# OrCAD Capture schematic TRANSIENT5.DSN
size A
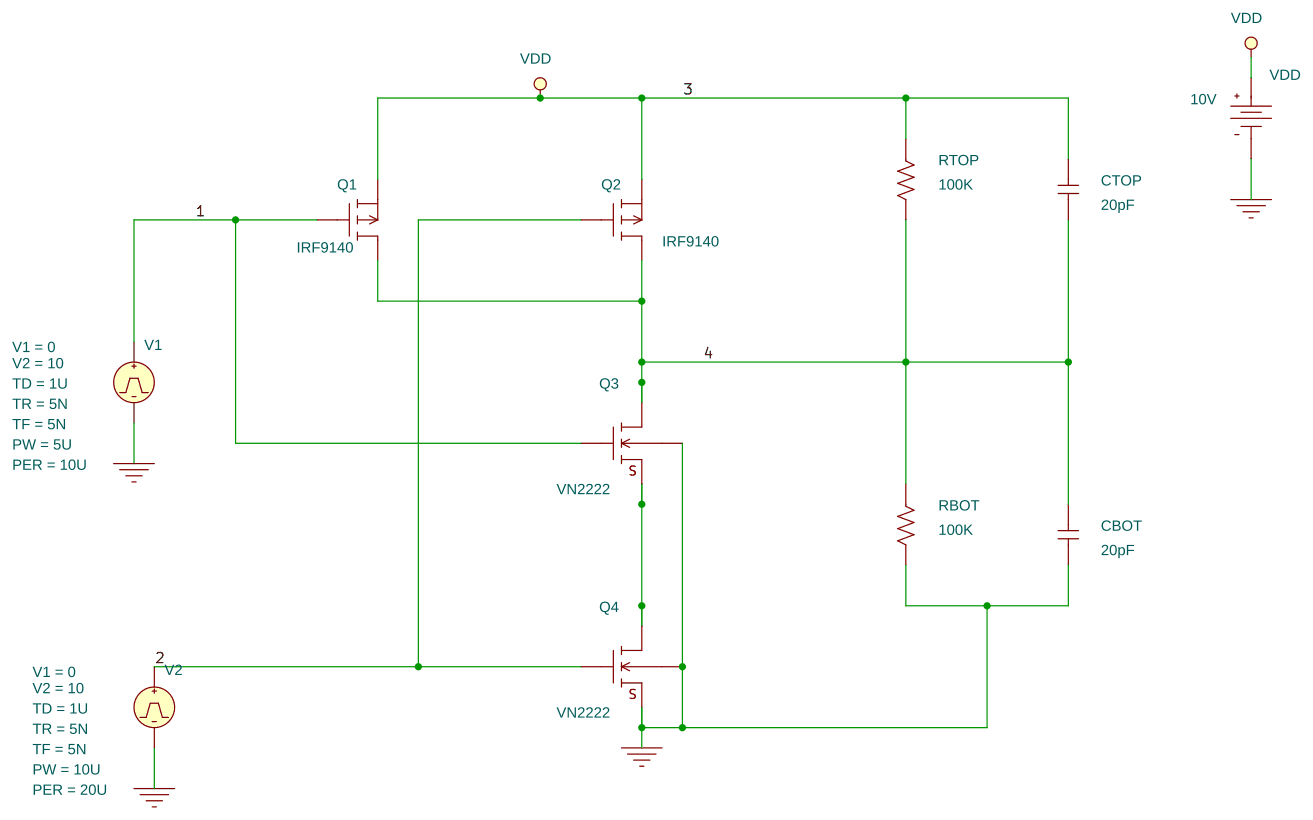
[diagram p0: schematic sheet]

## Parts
CBOT  20pF  [RAD/CK05]
CTOP  20pF  [RAD/CK05]
Q1  IRF9140  [TO204AA]
Q2  IRF9140  [TO204AA]
Q3  VN2222  [MFN4]
Q4  VN2222  [MFN4]
RBOT  100K  [AX/RC05]
RTOP  100K  [AX/RC05]
V1  VPULSE
V2  VPULSE
VDD  VDC

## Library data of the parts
CBOT CTOP = C
Q1 Q2 = IRF9140
Q3 Q4 = VN2222
RBOT RTOP = R
V1 = VPULSE: PER: 10U; PW: 5U; TD: 1U; TF: 5N; TR: 5N; V1: 0; V2: 10
V2 = VPULSE: PER: 20U; PW: 10U; TD: 1U; TF: 5N; TR: 5N; V1: 0; V2: 10
VDD = VDC: DC: 10V

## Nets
VDD: CTOP.1 Q1.2(S) Q2.2(S) RTOP.1 VDD.0(+)
0: CBOT.2 Q3.4(SUB) Q4.1(S) Q4.4(SUB) RBOT.2 V1.2(-) V2.2(-) VDD.1(-)
1: Q1.1(G) Q3.2(G) V1.1(+)
2: Q2.1(G) Q4.2(G) V2.1(+)
4: CBOT.1 CTOP.2 Q1.3(D) Q2.3(D) Q3.3(D) RBOT.1 RTOP.2
N05434: Q3.1(S) Q4.3(D)
